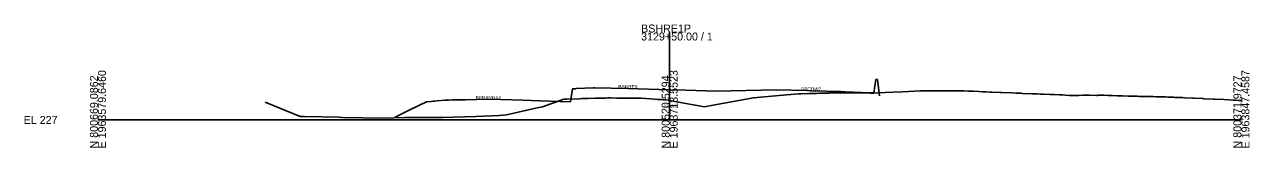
# Model space of a CAD drawing. Extents: x -26 to 403, y -10 to 6039.
# Drawn here: x -25.7 to 402.8, y 990.3 to 1033.5 of the extents above; entities that cross this region are included whole.
import ezdxf

# ---------------------------------------------------------------- set-up
doc = ezdxf.new("R2010")
doc.units = 0
for name, color, linetype in [('Default', 7, 'Continuous'), ('RD_GPK_XS_Cell', 7, 'Continuous'), ('RD_TX_Misc1', 7, 'Continuous'), ('RD_XS_ExGround', 7, 'Continuous'), ('RD_XS_Pave', 7, 'Continuous'), ('RD_XS_TX_Elev_EX', 7, 'Continuous')]:
    doc.layers.add(name, color=color, linetype=linetype)

msp = doc.modelspace()

# ---------------------------------------------------------------- linework, layer by layer
at = {"layer": 'RD_GPK_XS_Cell'}
for p, q in [((200, 1000), (200, 1030.68)), ((0, 1000), (200, 1000)), ((200, 1000), (400, 1000))]:
    msp.add_line(p, q, dxfattribs=at)
at = {"layer": 'RD_XS_ExGround'}
msp.add_lwpolyline([(58.44, 1006.21), (70.71, 1001.24), (72.2, 1001.22), (84.26, 1001), (85.51, 1000.89), (99.52, 1000.68), (107.48, 1000.83), (120.49, 1000.9), (132.16, 1001.17), (140.36, 1001.57), (142.9, 1001.77), (153.67, 1004.22), (155.54, 1004.63), (162.93, 1007.27), (164.16, 1007.29), (168.41, 1007.39), (168.53, 1007.41), (169.23, 1007.47), (170.15, 1007.49), (171.51, 1007.53), (173.81, 1007.61), (174.8, 1007.63), (177.55, 1007.69), (178.29, 1007.71), (179.05, 1007.72), (179.35, 1007.72), (181.51, 1007.7), (183.71, 1007.7), (185.01, 1007.7), (188.6, 1007.67), (190.01, 1007.64), (193.24, 1007.41), (195.82, 1007.22), (196.75, 1007.15), (197.8, 1007.07), (198.62, 1007.01), (199.62, 1006.93), (200, 1006.86), (201.83, 1006.51), (212.22, 1004.64), (215.78, 1005.27), (229.32, 1007.77), (238.28, 1008.6), (245.1, 1009.17), (245.25, 1009.12), (245.9, 1009.15), (248.9, 1009.25), (250.84, 1009.31), (251.32, 1009.32), (252.26, 1009.35), (255.63, 1009.45), (255.97, 1009.46), (257.58, 1009.5), (259.02, 1009.51), (259.48, 1009.51), (259.98, 1009.51), (260.73, 1009.51), (262.38, 1009.5), (262.91, 1009.5), (263.46, 1009.5), (265.7, 1009.48), (266.38, 1009.48), (267.16, 1009.47), (269.07, 1009.46), (270.18, 1009.45), (271.32, 1009.44), (275.37, 1009.63), (278.2, 1009.79), (281.49, 1009.92), (287.79, 1010.17), (288.11, 1010.18), (289.65, 1010.17), (290.17, 1010.22), (290.8, 1010.22), (291.2, 1010.22), (292.68, 1010.22), (292.99, 1010.23), (293.33, 1010.22), (296.05, 1010.21), (296.51, 1010.21), (296.95, 1010.21), (299.39, 1010.18), (300.87, 1010.17), (302.15, 1010.18), (302.89, 1010.16), (304.49, 1010.11), (306.12, 1010.05), (308.18, 1009.97), (309.47, 1009.91), (310.62, 1009.86), (312.12, 1009.79), (312.51, 1009.77), (312.84, 1009.76), (315.56, 1009.65), (316.17, 1009.63), (319.56, 1009.5), (321.27, 1009.42), (322.97, 1009.34), (323.41, 1009.32), (326.75, 1009.18), (328.4, 1009.13), (329.68, 1009.08), (330.65, 1009.04), (333.07, 1008.94), (333.68, 1008.92), (334.45, 1008.89), (336.38, 1008.81), (337.41, 1008.78), (338.36, 1008.72), (339.81, 1008.63), (340.07, 1008.59), (340.55, 1008.57), (341.7, 1008.56), (342.59, 1008.55), (343.11, 1008.55), (344.56, 1008.65), (345.98, 1008.74), (346.71, 1008.69), (346.94, 1008.64), (349.32, 1008.61), (349.68, 1008.57), (350.02, 1008.66), (350.42, 1008.66), (352.01, 1008.66), (353.25, 1008.62), (354.93, 1008.56), (356.6, 1008.51), (356.98, 1008.5), (358.42, 1008.46), (360.25, 1008.4), (360.57, 1008.39), (361.99, 1008.34), (363.26, 1008.3), (363.69, 1008.29), (364.25, 1008.28), (365.57, 1008.25), (366.68, 1008.23), (367.2, 1008.22), (367.89, 1008.2), (369.13, 1008.17), (370.04, 1008.15), (370.74, 1008.13), (371.7, 1008.1), (372.7, 1008.08), (373.42, 1008.06), (374.32, 1008.03), (375.52, 1007.98), (376.23, 1007.95), (376.8, 1007.93), (379.35, 1007.83), (380.17, 1007.79), (382.97, 1007.67), (383.54, 1007.64), (386.6, 1007.48), (386.9, 1007.46), (390.26, 1007.3), (390.74, 1007.28), (393.89, 1007.13), (395.64, 1007.04), (396.96, 1006.97), (398.17, 1006.91), (398.99, 1006.86), (400, 1006.8)], dxfattribs=at)
at = {"layer": 'RD_XS_Pave'}
for points in [[(237.37, 1010.61), (247.99, 1010.29), (249.38, 1010.25), (259.9, 1009.93), (261.39, 1009.89), (270.08, 1009.54), (271.4, 1009.49), (272.15, 1014.16), (272.65, 1014.16), (273.4, 1008.49)], [(103.92, 1000.93), (109.3, 1003.61), (114.88, 1006.38), (116.61, 1006.52), (117.41, 1006.58), (117.9, 1006.62), (118.63, 1006.68), (121.35, 1006.89), (122.64, 1006.99), (123.99, 1007.01), (124.64, 1007.03), (128.63, 1007.1), (136.66, 1007.25), (140.87, 1007.16), (148.68, 1006.99), (154.59, 1006.74), (165.29, 1006.3), (166.04, 1010.97), (166.53, 1010.97), (167.29, 1010.96)], [(167.29, 1011), (173.2, 1011.24), (173.65, 1011.26), (185.31, 1011.02), (200, 1010.59), (205.66, 1010.42), (216, 1010.11), (237.37, 1010.6)]]:
    msp.add_lwpolyline(points, dxfattribs=at)

# ---------------------------------------------------------------- texts
at = {"layer": 'Default'}
msp.add_text('-', height=0.0001, dxfattribs=at).set_placement((0, 1000))
at = {"layer": 'RD_GPK_XS_Cell'}
for s, p in [('BSHRE1P', (190, 1030.68)), ('3129+50.00 / 1', (190, 1027.88)), ('EL 227', (-26, 998.6))]:
    msp.add_text(s, height=2.8, dxfattribs=at).set_placement(p)
for s, p in [('E 1963579.6460', (2.8, 990)), ('E 1963713.5523', (202.8, 990)), ('E 1963847.4587', (402.8, 990)), ('N 800669.0862', (0, 990)), ('N 800520.5294', (200, 990)), ('N 800371.9727', (400, 990))]:
    msp.add_text(s, height=2.8, rotation=90, dxfattribs=at).set_placement(p)
at = {"layer": 'RD_TX_Misc1'}
for s, p in [('BSHRE0', (182.08, 1011.02)), ('I20CDW2', (245.86, 1010.25)), ('BERRYHILL', (132.16, 1007.22))]:
    msp.add_text(s, height=1.2, dxfattribs=at).set_placement(p)
at = {"layer": 'RD_XS_TX_Elev_EX'}
msp.add_text('233.86', height=1, dxfattribs=at).set_placement((197.9, 1004.36))

doc.saveas('drawing.dxf')
